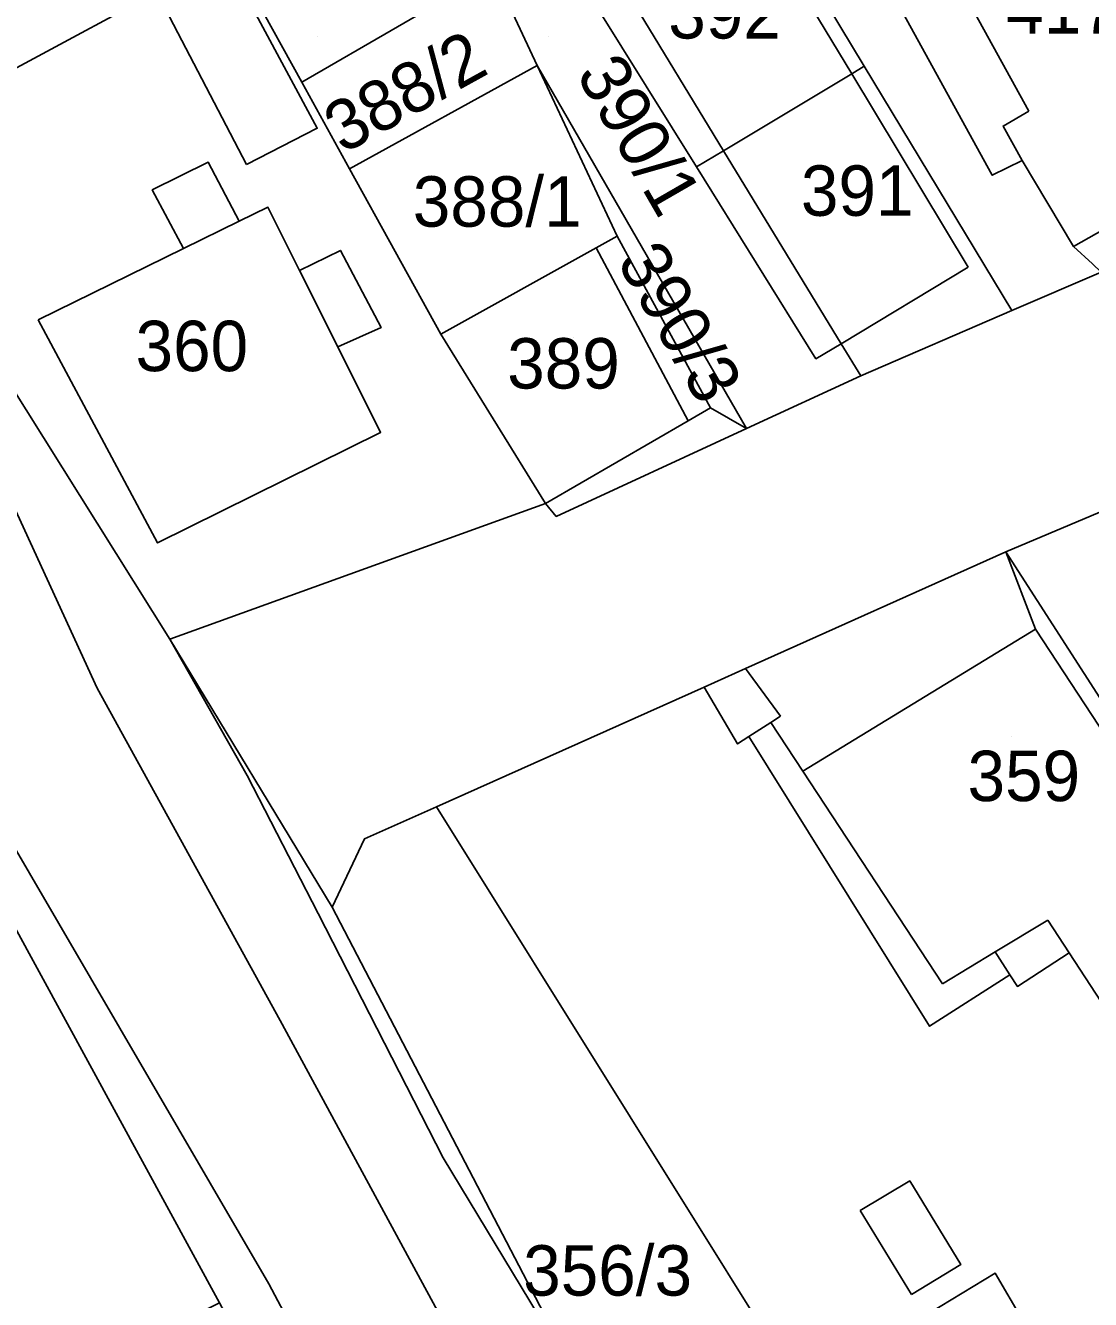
# Model space of a CAD drawing. Extents: x -263943 to -261149, y -1236934 to -1230686.
# Drawn here: x -262788.8 to -262746.5, y -1235682.1 to -1235631.6 of the extents above; entities that cross this region are included whole.
import ezdxf

# ---------------------------------------------------------------- set-up
doc = ezdxf.new("R2010")
doc.units = 0
for name, color, linetype in [('body_kn', 7, 'Continuous'), ('kladpar_druhypozemkov', 7, 'Continuous'), ('kladpar_hranice', 7, 'Continuous'), ('kladpar_parcelnecisla', 7, 'Continuous'), ('kladpar_plochy', 7, 'Continuous'), ('zappar_hrandruhpozemk', 7, 'Continuous')]:
    doc.layers.add(name, color=color, linetype=linetype)

msp = doc.modelspace()

# ---------------------------------------------------------------- linework, layer by layer
at = {"layer": 'body_kn'}
for p, q in [((-262768.47, -1235633.15), (-262768.47, -1235633.15)), ((-262768.47, -1235633.15), (-262768.47, -1235633.15)), ((-262756.01, -1235633.48), (-262756.01, -1235633.48)), ((-262756.01, -1235633.48), (-262756.01, -1235633.48)), ((-262755.51, -1235633.18), (-262755.51, -1235633.18)), ((-262777.8, -1235633.81), (-262777.8, -1235633.81)), ((-262748.99, -1235634.96), (-262748.99, -1235634.96)), ((-262777.19, -1235635.64), (-262777.19, -1235635.64)), ((-262750.01, -1235635.55), (-262750.01, -1235635.55)), ((-262781.52, -1235636.98), (-262781.52, -1235636.98)), ((-262761.09, -1235636.53), (-262761.09, -1235636.53)), ((-262761.09, -1235636.53), (-262761.09, -1235636.53)), ((-262749.25, -1235636.91), (-262749.25, -1235636.91)), ((-262749.25, -1235636.91), (-262749.25, -1235636.91)), ((-262779.99, -1235637.07), (-262779.99, -1235637.07)), ((-262775.91, -1235637.24), (-262775.91, -1235637.24)), ((-262775.91, -1235637.24), (-262775.91, -1235637.24)), ((-262762.16, -1235637.17), (-262762.16, -1235637.17)), ((-262750.44, -1235637.5), (-262750.44, -1235637.5)), ((-262783.73, -1235638.08), (-262783.73, -1235638.08)), ((-262779.15, -1235638.77), (-262779.15, -1235638.77)), ((-262780.28, -1235639.32), (-262780.28, -1235639.32)), ((-262780.28, -1235639.32), (-262780.28, -1235639.32)), ((-262765.31, -1235639.92), (-262765.31, -1235639.92)), ((-262782.49, -1235640.41), (-262782.49, -1235640.41)), ((-262782.49, -1235640.41), (-262782.49, -1235640.41)), ((-262776.27, -1235640.48), (-262776.27, -1235640.48)), ((-262766.14, -1235640.38), (-262766.14, -1235640.38)), ((-262766.14, -1235640.38), (-262766.14, -1235640.38)), ((-262747.22, -1235640.32), (-262747.22, -1235640.32)), ((-262777.89, -1235641.28), (-262777.89, -1235641.28)), ((-262751.39, -1235641.15), (-262751.39, -1235641.15)), ((-262749.66, -1235642.87), (-262749.66, -1235642.87)), ((-262788.25, -1235643.24), (-262788.25, -1235643.24)), ((-262788.25, -1235643.24), (-262788.25, -1235643.24)), ((-262774.66, -1235643.54), (-262774.66, -1235643.54)), ((-262772.29, -1235643.8), (-262772.29, -1235643.8)), ((-262772.29, -1235643.8), (-262772.29, -1235643.8)), ((-262776.38, -1235644.31), (-262776.38, -1235644.31)), ((-262776.38, -1235644.31), (-262776.38, -1235644.31)), ((-262756.43, -1235644.18), (-262756.43, -1235644.18)), ((-262756.43, -1235644.18), (-262756.43, -1235644.18)), ((-262757.43, -1235644.78), (-262757.43, -1235644.78)), ((-262755.65, -1235645.46), (-262755.65, -1235645.46)), ((-262755.65, -1235645.46), (-262755.65, -1235645.46)), ((-262761.6, -1235646.72), (-262761.6, -1235646.72)), ((-262761.6, -1235646.72), (-262761.6, -1235646.72)), ((-262762.49, -1235647.24), (-262762.49, -1235647.24)), ((-262762.49, -1235647.24), (-262762.49, -1235647.24)), ((-262760.18, -1235647.55), (-262760.18, -1235647.55)), ((-262760.18, -1235647.55), (-262760.18, -1235647.55)), ((-262774.68, -1235647.7), (-262774.68, -1235647.7)), ((-262768.15, -1235650.52), (-262768.15, -1235650.52)), ((-262767.72, -1235651.03), (-262767.72, -1235651.03)), ((-262783.52, -1235652.08), (-262783.52, -1235652.08)), ((-262749.9, -1235652.44), (-262749.9, -1235652.44)), ((-262749.9, -1235652.44), (-262749.9, -1235652.44)), ((-262748.72, -1235655.5), (-262748.72, -1235655.5)), ((-262783.03, -1235655.9), (-262783.03, -1235655.9)), ((-262783.03, -1235655.9), (-262783.03, -1235655.9)), ((-262760.22, -1235657.06), (-262760.22, -1235657.06)), ((-262785.92, -1235657.84), (-262785.92, -1235657.84)), ((-262761.86, -1235657.8), (-262761.86, -1235657.8)), ((-262759.21, -1235659.2), (-262759.21, -1235659.2)), ((-262758.83, -1235658.95), (-262758.83, -1235658.95)), ((-262760.53, -1235660.05), (-262760.53, -1235660.05)), ((-262760.08, -1235659.76), (-262760.08, -1235659.76)), ((-262760.08, -1235659.76), (-262760.08, -1235659.76)), ((-262757.94, -1235661.13), (-262757.94, -1235661.13)), ((-262779.97, -1235661.3), (-262779.97, -1235661.3)), ((-262772.46, -1235662.54), (-262772.46, -1235662.54)), ((-262775.32, -1235663.82), (-262775.32, -1235663.82)), ((-262777.16, -1235666.77), (-262777.16, -1235666.77)), ((-262776.6, -1235666.53), (-262776.6, -1235666.53)), ((-262748.24, -1235667.04), (-262748.24, -1235667.04)), ((-262750.32, -1235668.3), (-262750.32, -1235668.3)), ((-262747.39, -1235668.34), (-262747.39, -1235668.34)), ((-262747.39, -1235668.34), (-262747.39, -1235668.34)), ((-262749.74, -1235669.21), (-262749.74, -1235669.21)), ((-262752.41, -1235669.57), (-262752.41, -1235669.57)), ((-262749.44, -1235669.67), (-262749.44, -1235669.67)), ((-262778.66, -1235671.02), (-262778.66, -1235671.02)), ((-262752.92, -1235671.25), (-262752.92, -1235671.25)), ((-262772.2, -1235676.47), (-262772.2, -1235676.47)), ((-262753.71, -1235677.38), (-262753.71, -1235677.38)), ((-262755.67, -1235678.56), (-262755.67, -1235678.56)), ((-262755.67, -1235678.56), (-262755.67, -1235678.56)), ((-262751.68, -1235680.69), (-262751.68, -1235680.69)), ((-262779.11, -1235681.46), (-262779.11, -1235681.46)), ((-262750.32, -1235681.04), (-262750.32, -1235681.04)), ((-262753.64, -1235681.88), (-262753.64, -1235681.88))]:
    msp.add_line(p, q, dxfattribs=at)
at = {"layer": 'kladpar_druhypozemkov'}
for p, q in [((-262777.17, -1235631.98), (-262777.17, -1235631.98)), ((-262768.02, -1235631.98), (-262768.02, -1235631.98)), ((-262773.84, -1235633.34), (-262773.84, -1235633.34)), ((-262756.08, -1235637.3), (-262756.08, -1235637.3)), ((-262770.36, -1235637.79), (-262770.36, -1235637.79)), ((-262764.35, -1235641.07), (-262764.35, -1235641.07)), ((-262782.16, -1235643.47), (-262782.16, -1235643.47)), ((-262767.03, -1235643.93), (-262767.03, -1235643.93)), ((-262749.66, -1235659.77), (-262749.66, -1235659.77)), ((-262764.73, -1235680.2), (-262764.73, -1235680.2))]:
    msp.add_line(p, q, dxfattribs=at)
at = {"layer": 'kladpar_hranice'}
for points in [[(-262875.23, -1235515.04), (-262864.6, -1235511.6), (-262864.18, -1235512.62), (-262863.6, -1235514.57), (-262862.09, -1235517.91), (-262860.85, -1235520.66), (-262856.72, -1235529.81), (-262851.77, -1235540.78), (-262845.31, -1235555.09), (-262839.58, -1235565.52), (-262837.34, -1235569.58), (-262834.81, -1235574.17), (-262829.9, -1235583.1), (-262829.56, -1235582.85), (-262826.95, -1235587.1), (-262821.46, -1235596.03), (-262818.34, -1235601.22), (-262810.4, -1235614.14), (-262809.89, -1235613.81), (-262808.03, -1235616.78), (-262795.62, -1235636.77), (-262795.19, -1235636.51), (-262783.03, -1235655.9)], [(-262780.64, -1235628.67), (-262795.19, -1235636.51), (-262795.62, -1235636.77), (-262808.03, -1235616.78), (-262792.46, -1235607.75), (-262789.76, -1235612.09), (-262783.94, -1235622.63), (-262780.64, -1235628.67)], [(-262747.36, -1235628.43), (-262742.12, -1235637.45), (-262740.6, -1235638.98), (-262746.12, -1235641.34), (-262749.66, -1235642.87), (-262755.51, -1235633.18), (-262760.34, -1235625.16), (-262762.17, -1235622.12), (-262753.18, -1235618.06), (-262752.19, -1235619.83), (-262749.93, -1235623.85), (-262747.36, -1235628.43)], [(-262755.65, -1235645.46), (-262760.18, -1235647.55), (-262768.47, -1235633.15), (-262770.22, -1235629.41), (-262771.77, -1235626.1), (-262772.06, -1235625.47), (-262773.02, -1235623.69), (-262767.95, -1235620.82), (-262766.03, -1235624.03), (-262767.14, -1235624.73), (-262766.99, -1235624.95), (-262767.82, -1235625.45), (-262769, -1235626.16), (-262767.11, -1235629.21), (-262762.16, -1235637.17), (-262757.43, -1235644.78), (-262756.43, -1235644.18), (-262755.65, -1235645.46)], [(-262756.01, -1235633.48), (-262761.09, -1235636.53), (-262762.16, -1235637.17), (-262767.11, -1235629.21), (-262765.95, -1235628.52), (-262765.07, -1235627.99), (-262760.84, -1235625.46), (-262760.34, -1235625.16), (-262755.51, -1235633.18), (-262756.01, -1235633.48)], [(-262779.72, -1235630.33), (-262771.77, -1235626.1), (-262770.22, -1235629.41), (-262777.8, -1235633.81), (-262779.72, -1235630.33)], [(-262757.76, -1235730.23), (-262761.56, -1235721.9), (-262763.04, -1235718.53), (-262763.46, -1235717.58), (-262766.12, -1235711.54), (-262769.67, -1235704.31), (-262775.58, -1235692.33), (-262777.72, -1235688.39), (-262778.58, -1235686.8), (-262780.87, -1235682.58), (-262781.07, -1235682.21), (-262789.26, -1235667.17), (-262792.46, -1235658.93), (-262798.2, -1235647.88), (-262804.87, -1235637.59), (-262810.68, -1235627.46)], [(-262772.29, -1235643.8), (-262768.15, -1235650.52), (-262783.03, -1235655.9), (-262795.19, -1235636.51), (-262780.64, -1235628.67), (-262779.72, -1235630.33), (-262777.8, -1235633.81), (-262775.91, -1235637.24), (-262772.29, -1235643.8)], [(-262775.91, -1235637.24), (-262777.8, -1235633.81), (-262770.22, -1235629.41), (-262768.47, -1235633.15), (-262775.91, -1235637.24)], [(-262772.29, -1235643.8), (-262775.91, -1235637.24), (-262768.47, -1235633.15), (-262765.31, -1235639.92), (-262766.14, -1235640.38), (-262772.29, -1235643.8)], [(-262768.47, -1235633.15), (-262760.18, -1235647.55), (-262761.6, -1235646.72), (-262765.31, -1235639.92), (-262768.47, -1235633.15)], [(-262755.65, -1235645.46), (-262756.43, -1235644.18), (-262757.43, -1235644.78), (-262762.16, -1235637.17), (-262761.09, -1235636.53), (-262756.01, -1235633.48), (-262755.51, -1235633.18), (-262749.66, -1235642.87), (-262755.65, -1235645.46)], [(-262760.18, -1235647.55), (-262767.72, -1235651.03), (-262768.15, -1235650.52), (-262772.29, -1235643.8), (-262766.14, -1235640.38), (-262765.31, -1235639.92), (-262761.6, -1235646.72), (-262760.18, -1235647.55)], [(-262742.04, -1235649.12), (-262749.9, -1235652.44), (-262760.22, -1235657.06), (-262761.86, -1235657.8), (-262772.46, -1235662.54), (-262775.32, -1235663.82), (-262776.6, -1235666.53), (-262783.03, -1235655.9), (-262768.15, -1235650.52), (-262767.72, -1235651.03), (-262760.18, -1235647.55), (-262755.65, -1235645.46), (-262749.66, -1235642.87), (-262746.12, -1235641.34)], [(-262720.9, -1235669.5), (-262721.34, -1235669.78), (-262726.46, -1235672.97), (-262733.75, -1235677.52), (-262749.9, -1235652.44), (-262742.04, -1235649.12), (-262736.28, -1235646.69), (-262735.95, -1235646.55), (-262721.49, -1235668.6), (-262720.9, -1235669.5)], [(-262720.82, -1235696.82), (-262721.4, -1235697.17), (-262726.59, -1235700.34), (-262733.62, -1235689.41), (-262737.55, -1235683.39), (-262739.38, -1235684.55), (-262740.48, -1235683.02), (-262738.6, -1235681.79), (-262739.51, -1235680.4), (-262740.39, -1235680.9), (-262741.91, -1235678.69), (-262741.02, -1235678.09), (-262747.39, -1235668.34), (-262749.44, -1235669.67), (-262749.74, -1235669.21), (-262752.92, -1235671.25), (-262760.08, -1235659.76), (-262760.53, -1235660.05), (-262761.86, -1235657.8), (-262760.22, -1235657.06), (-262749.9, -1235652.44), (-262733.75, -1235677.52), (-262728.2, -1235685.95), (-262720.82, -1235696.82)], [(-262783.03, -1235655.9), (-262779.97, -1235661.3), (-262777.16, -1235666.77), (-262772.2, -1235676.47), (-262767.05, -1235684.99), (-262766.76, -1235685.6), (-262764.24, -1235690.94), (-262761.83, -1235696.04), (-262757.57, -1235705.05), (-262755.44, -1235709.57), (-262750.25, -1235720.55), (-262748.69, -1235723.86), (-262748.15, -1235725)], [(-262783.03, -1235655.9), (-262776.6, -1235666.53), (-262760.31, -1235697.81), (-262756.81, -1235704.55), (-262757.57, -1235705.05)], [(-262757.57, -1235705.05), (-262761.83, -1235696.04), (-262764.24, -1235690.94), (-262766.76, -1235685.6), (-262767.05, -1235684.99), (-262772.2, -1235676.47), (-262777.16, -1235666.77), (-262779.97, -1235661.3), (-262783.03, -1235655.9)], [(-262720.1, -1235733.26), (-262729.95, -1235715.09), (-262732.09, -1235716.21), (-262737.27, -1235718.92), (-262749.44, -1235699.43), (-262772.46, -1235662.54), (-262761.86, -1235657.8), (-262760.53, -1235660.05), (-262760.08, -1235659.76), (-262752.92, -1235671.25), (-262749.74, -1235669.21), (-262749.44, -1235669.67), (-262747.39, -1235668.34), (-262741.02, -1235678.09), (-262741.91, -1235678.69), (-262740.39, -1235680.9), (-262739.51, -1235680.4), (-262738.6, -1235681.79), (-262740.48, -1235683.02), (-262739.38, -1235684.55), (-262737.55, -1235683.39)], [(-262776.6, -1235666.53), (-262775.32, -1235663.82), (-262772.46, -1235662.54), (-262749.44, -1235699.43), (-262756.81, -1235704.55), (-262760.31, -1235697.81), (-262776.6, -1235666.53)], [(-262790.28, -1235666.57), (-262789.26, -1235667.17), (-262781.07, -1235682.21), (-262782.43, -1235682.89), (-262808.36, -1235695.96), (-262810.28, -1235692.12), (-262800.1, -1235686.99), (-262801.36, -1235681.47), (-262799.74, -1235680.63), (-262804.2, -1235671.36), (-262804.89, -1235669.92), (-262800.47, -1235667.73), (-262796.56, -1235666.3), (-262794.01, -1235666.05), (-262791.8, -1235665.97), (-262790.28, -1235666.57)]]:
    msp.add_lwpolyline(points, dxfattribs=at)
at = {"layer": 'kladpar_plochy'}
for points in [[(-262780.64, -1235628.67), (-262795.19, -1235636.51), (-262795.62, -1235636.77), (-262808.03, -1235616.78), (-262792.46, -1235607.75), (-262789.76, -1235612.09), (-262783.94, -1235622.63)], [(-262747.36, -1235628.43), (-262742.12, -1235637.45), (-262740.6, -1235638.98), (-262746.12, -1235641.34), (-262749.66, -1235642.87), (-262755.51, -1235633.18), (-262760.34, -1235625.16), (-262762.17, -1235622.12), (-262753.18, -1235618.06), (-262752.19, -1235619.83), (-262749.93, -1235623.85)], [(-262755.65, -1235645.46), (-262760.18, -1235647.55), (-262768.47, -1235633.15), (-262770.22, -1235629.41), (-262771.77, -1235626.1), (-262772.06, -1235625.47), (-262773.02, -1235623.69), (-262767.95, -1235620.82), (-262766.03, -1235624.03), (-262767.14, -1235624.73), (-262766.99, -1235624.95), (-262767.82, -1235625.45), (-262769, -1235626.16), (-262767.11, -1235629.21), (-262762.16, -1235637.17), (-262757.43, -1235644.78), (-262756.43, -1235644.18)], [(-262756.01, -1235633.48), (-262761.09, -1235636.53), (-262762.16, -1235637.17), (-262767.11, -1235629.21), (-262765.95, -1235628.52), (-262765.07, -1235627.99), (-262760.84, -1235625.46), (-262760.34, -1235625.16), (-262755.51, -1235633.18)], [(-262779.72, -1235630.33), (-262771.77, -1235626.1), (-262770.22, -1235629.41), (-262777.8, -1235633.81)], [(-262772.29, -1235643.8), (-262768.15, -1235650.52), (-262783.03, -1235655.9), (-262795.19, -1235636.51), (-262780.64, -1235628.67), (-262779.72, -1235630.33), (-262777.8, -1235633.81), (-262775.91, -1235637.24)], [(-262775.91, -1235637.24), (-262777.8, -1235633.81), (-262770.22, -1235629.41), (-262768.47, -1235633.15)], [(-262772.29, -1235643.8), (-262775.91, -1235637.24), (-262768.47, -1235633.15), (-262765.31, -1235639.92), (-262766.14, -1235640.38)], [(-262768.47, -1235633.15), (-262760.18, -1235647.55), (-262761.6, -1235646.72), (-262765.31, -1235639.92)], [(-262755.65, -1235645.46), (-262756.43, -1235644.18), (-262757.43, -1235644.78), (-262762.16, -1235637.17), (-262761.09, -1235636.53), (-262756.01, -1235633.48), (-262755.51, -1235633.18), (-262749.66, -1235642.87)], [(-262760.18, -1235647.55), (-262767.72, -1235651.03), (-262768.15, -1235650.52), (-262772.29, -1235643.8), (-262766.14, -1235640.38), (-262765.31, -1235639.92), (-262761.6, -1235646.72)], [(-262720.9, -1235669.5), (-262721.34, -1235669.78), (-262726.46, -1235672.97), (-262733.75, -1235677.52), (-262749.9, -1235652.44), (-262742.04, -1235649.12), (-262736.28, -1235646.69), (-262735.95, -1235646.55), (-262721.49, -1235668.6)], [(-262720.82, -1235696.82), (-262721.4, -1235697.17), (-262726.59, -1235700.34), (-262733.62, -1235689.41), (-262737.55, -1235683.39), (-262739.38, -1235684.55), (-262740.48, -1235683.02), (-262738.6, -1235681.79), (-262739.51, -1235680.4), (-262740.39, -1235680.9), (-262741.91, -1235678.69), (-262741.02, -1235678.09), (-262747.39, -1235668.34), (-262749.44, -1235669.67), (-262749.74, -1235669.21), (-262752.92, -1235671.25), (-262760.08, -1235659.76), (-262760.53, -1235660.05), (-262761.86, -1235657.8), (-262760.22, -1235657.06), (-262749.9, -1235652.44), (-262733.75, -1235677.52), (-262728.2, -1235685.95)], [(-262783.03, -1235655.9), (-262776.6, -1235666.53), (-262760.31, -1235697.81), (-262756.81, -1235704.55), (-262757.57, -1235705.05), (-262761.83, -1235696.04), (-262764.24, -1235690.94), (-262766.76, -1235685.6), (-262767.05, -1235684.99), (-262772.2, -1235676.47), (-262777.16, -1235666.77), (-262779.97, -1235661.3)], [(-262776.6, -1235666.53), (-262775.32, -1235663.82), (-262772.46, -1235662.54), (-262749.44, -1235699.43), (-262756.81, -1235704.55), (-262760.31, -1235697.81)], [(-262790.28, -1235666.57), (-262789.26, -1235667.17), (-262781.07, -1235682.21), (-262782.43, -1235682.89), (-262808.36, -1235695.96), (-262810.28, -1235692.12), (-262800.1, -1235686.99), (-262801.36, -1235681.47), (-262799.74, -1235680.63), (-262804.2, -1235671.36), (-262804.89, -1235669.92), (-262800.47, -1235667.73), (-262796.56, -1235666.3), (-262794.01, -1235666.05), (-262791.8, -1235665.97)]]:
    msp.add_lwpolyline(points, close=True, dxfattribs=at)
for points in [[(-262808.03, -1235616.78), (-262795.62, -1235636.77), (-262795.19, -1235636.51), (-262783.03, -1235655.9), (-262779.97, -1235661.3), (-262777.16, -1235666.77), (-262772.2, -1235676.47), (-262767.05, -1235684.99), (-262766.76, -1235685.6), (-262764.24, -1235690.94), (-262761.83, -1235696.04), (-262757.57, -1235705.05), (-262755.44, -1235709.57), (-262750.25, -1235720.55), (-262748.69, -1235723.86), (-262748.15, -1235725), (-262744.69, -1235734)], [(-262757.76, -1235730.23), (-262761.56, -1235721.9), (-262763.04, -1235718.53), (-262763.46, -1235717.58), (-262766.12, -1235711.54), (-262769.67, -1235704.31), (-262775.58, -1235692.33), (-262777.72, -1235688.39), (-262778.58, -1235686.8), (-262780.87, -1235682.58), (-262781.07, -1235682.21), (-262789.26, -1235667.17), (-262792.46, -1235658.93), (-262798.2, -1235647.88), (-262804.87, -1235637.59), (-262810.68, -1235627.46)], [(-262742.04, -1235649.12), (-262749.9, -1235652.44), (-262760.22, -1235657.06), (-262761.86, -1235657.8), (-262772.46, -1235662.54), (-262775.32, -1235663.82), (-262776.6, -1235666.53), (-262783.03, -1235655.9), (-262768.15, -1235650.52), (-262767.72, -1235651.03), (-262760.18, -1235647.55), (-262755.65, -1235645.46), (-262749.66, -1235642.87), (-262746.12, -1235641.34)], [(-262737.27, -1235718.92), (-262749.44, -1235699.43), (-262772.46, -1235662.54), (-262761.86, -1235657.8), (-262760.53, -1235660.05), (-262760.08, -1235659.76), (-262752.92, -1235671.25), (-262749.74, -1235669.21), (-262749.44, -1235669.67), (-262747.39, -1235668.34), (-262741.02, -1235678.09)]]:
    msp.add_lwpolyline(points, dxfattribs=at)
at = {"layer": 'zappar_hrandruhpozemk'}
for p, q in [((-262756.01, -1235633.48), (-262760.84, -1235625.46)), ((-262761.09, -1235636.53), (-262765.95, -1235628.52)), ((-262751.61, -1235630.2), (-262748.99, -1235634.96)), ((-262779.99, -1235637.07), (-262783.37, -1235630.61)), ((-262751.39, -1235641.15), (-262756.01, -1235633.48)), ((-262795.62, -1235636.77), (-262785.92, -1235657.84)), ((-262761.09, -1235636.53), (-262756.43, -1235644.18)), ((-262747.22, -1235640.32), (-262749.25, -1235636.91)), ((-262747.22, -1235640.32), (-262742.44, -1235637.63)), ((-262766.14, -1235640.38), (-262762.49, -1235647.24)), ((-262777.89, -1235641.28), (-262776.38, -1235644.31)), ((-262756.43, -1235644.18), (-262751.39, -1235641.15)), ((-262761.6, -1235646.72), (-262762.49, -1235647.24)), ((-262762.49, -1235647.24), (-262768.15, -1235650.52)), ((-262749.9, -1235652.44), (-262748.72, -1235655.5)), ((-262758.83, -1235658.95), (-262760.22, -1235657.06)), ((-262785.92, -1235657.84), (-262778.66, -1235671.02)), ((-262757.94, -1235661.13), (-262759.21, -1235659.2)), ((-262752.41, -1235669.57), (-262757.94, -1235661.13)), ((-262748.24, -1235667.04), (-262750.32, -1235668.3)), ((-262747.39, -1235668.34), (-262748.24, -1235667.04)), ((-262750.32, -1235668.3), (-262752.41, -1235669.57)), ((-262750.32, -1235668.3), (-262749.74, -1235669.21)), ((-262753.64, -1235681.88), (-262755.67, -1235678.56)), ((-262769.48, -1235699.56), (-262779.11, -1235681.46))]:
    msp.add_line(p, q, dxfattribs=at)
for points in [[(-262749.25, -1235636.91), (-262750.44, -1235637.5), (-262753.99, -1235631.04), (-262752.97, -1235630.37), (-262754.91, -1235626.63)], [(-262783.37, -1235630.61), (-262780.65, -1235629.18), (-262777.19, -1235635.64), (-262779.99, -1235637.07)], [(-262748.99, -1235634.96), (-262750.01, -1235635.55), (-262749.25, -1235636.91)], [(-262782.49, -1235640.41), (-262783.73, -1235638.08), (-262781.52, -1235636.98), (-262780.28, -1235639.32)], [(-262780.28, -1235639.32), (-262779.15, -1235638.77), (-262777.89, -1235641.28)], [(-262788.25, -1235643.24), (-262782.49, -1235640.41), (-262780.28, -1235639.32)], [(-262777.89, -1235641.28), (-262776.27, -1235640.48), (-262774.66, -1235643.54), (-262776.38, -1235644.31)], [(-262746.12, -1235641.34), (-262746.46, -1235641.02), (-262747.22, -1235640.32)], [(-262776.38, -1235644.31), (-262774.68, -1235647.7), (-262783.52, -1235652.08), (-262788.25, -1235643.24)], [(-262757.94, -1235661.13), (-262748.72, -1235655.5), (-262728.59, -1235686.2)], [(-262779.11, -1235681.46), (-262789.76, -1235663.18), (-262792.46, -1235658.93)], [(-262760.08, -1235659.76), (-262759.21, -1235659.2), (-262758.83, -1235658.95)], [(-262778.66, -1235671.02), (-262764.3, -1235697.54), (-262751.37, -1235723.46)], [(-262755.67, -1235678.56), (-262753.71, -1235677.38), (-262751.68, -1235680.69), (-262753.64, -1235681.88)], [(-262753.81, -1235683.15), (-262750.32, -1235681.04), (-262749.22, -1235682.91)]]:
    msp.add_lwpolyline(points, dxfattribs=at)

# ---------------------------------------------------------------- texts
at = {"layer": 'kladpar_parcelnecisla'}
for s, p in [('417', (-262749.882, -1235631.88)), ('392', (-262763.278, -1235632.08)), ('388/1', (-262773.405, -1235639.54)), ('391', (-262758.022, -1235639.11)), ('360', (-262784.393, -1235645.27)), ('389', (-262769.663, -1235645.96)), ('359', (-262751.417, -1235662.32)), ('356/3', (-262769.029, -1235681.93))]:
    msp.add_text(s, height=2, dxfattribs=at).set_placement(p)
for s, rotation, p in [('388/2', 29, (-262776.168, -1235636.675)), ('390/1', 300, (-262766.958, -1235633.491)), ('390/3', 300, (-262765.344, -1235640.918))]:
    msp.add_text(s, height=2, rotation=rotation, dxfattribs=at).set_placement(p)

doc.saveas('drawing.dxf')
